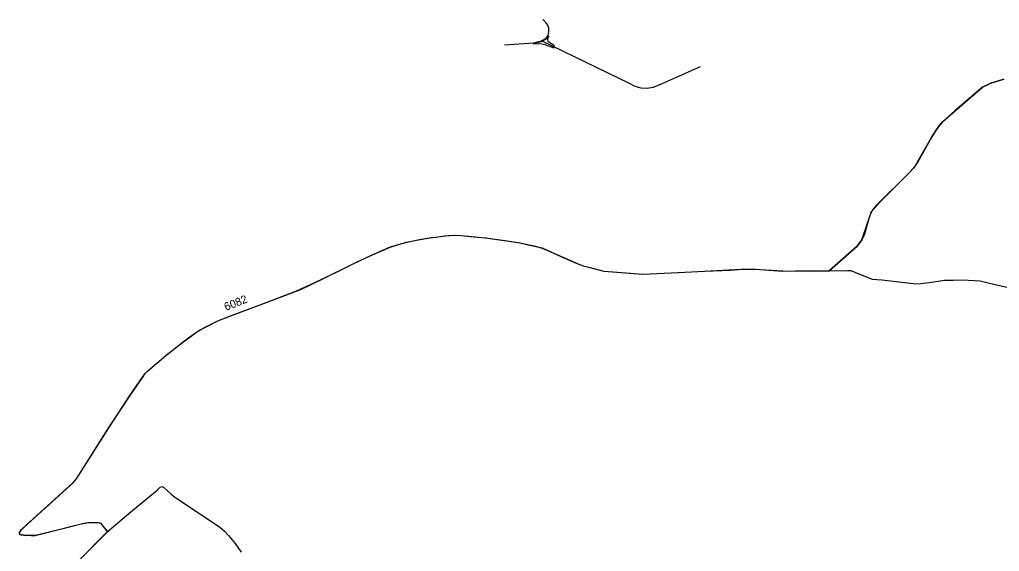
# Model space of a CAD drawing. Extents: x -444937 to -440733, y -1145714 to -1129798.
# Drawn here: x -444396 to -443173, y -1132712 to -1132048 of the extents above; entities that cross this region are included whole.
import ezdxf

# ---------------------------------------------------------------- set-up
doc = ezdxf.new("R2010")
doc.units = 0
doc.layers.add('Vrstva 12', color=7, linetype='Continuous')
doc.layers.add('Vrstva 75', color=7, linetype='Continuous')

msp = doc.modelspace()

# ---------------------------------------------------------------- linework, layer by layer
at = {"layer": 'Vrstva 12'}
for points in [[(-443790.5, -1132079.3), (-443754.5, -1132076.8), (-443744.6, -1132074.4), (-443738.7, -1132071), (-443736.3, -1132067.6), (-443735.4, -1132063.3), (-443735.4, -1132058.4), (-443736.6, -1132054.7), (-443739, -1132051.6), (-443742.8, -1132047.9)], [(-443546.4, -1132106.7), (-443594.8, -1132128.6), (-443605, -1132132.6), (-443612.4, -1132133.9), (-443620.1, -1132133.6), (-443627.5, -1132131.4), (-443635.5, -1132127.4), (-443744.6, -1132074.4)], [(-443167, -1132122.3), (-443176.2, -1132125.1), (-443183.1, -1132127.4), (-443193.7, -1132132.4), (-443228.1, -1132161.8), (-443243.2, -1132175.1), (-443248.2, -1132181.2), (-443252.1, -1132186.4), (-443257.1, -1132194.3), (-443275, -1132226.5), (-443280.2, -1132233.8), (-443285.8, -1132239.7), (-443325.5, -1132279.4), (-443330.7, -1132285.2), (-443333.2, -1132289.9), (-443335, -1132295.1), (-443341, -1132316.1), (-443344.2, -1132323), (-443350.1, -1132331.2), (-443385.1, -1132361.7)], [(-444286.4, -1132687.8), (-444291.4, -1132681.3), (-444294.5, -1132677.6), (-444297.8, -1132676.9), (-444301.8, -1132676.7), (-444311, -1132676.8), (-444317.7, -1132678.2), (-444337.3, -1132683), (-444376.8, -1132692.9), (-444381.9, -1132692.9), (-444386.3, -1132692.8), (-444390.1, -1132692.6), (-444391.2, -1132692.5), (-444394, -1132692.2), (-444394.6, -1132692.1), (-444395.8, -1132691.5), (-444396.3, -1132690.2), (-444396.3, -1132689.1), (-444395.6, -1132687.4), (-444390.6, -1132682), (-444328.9, -1132626.3), (-444325.6, -1132622.4), (-444322.2, -1132617.1), (-444284, -1132556.4), (-444258.4, -1132517.7), (-444241.6, -1132493.3), (-444239.4, -1132490.2), (-444236.1, -1132487), (-444213.9, -1132467.8), (-444192.2, -1132450.5), (-444183.6, -1132444.3), (-444175.6, -1132438.3), (-444169.9, -1132435.3), (-444163, -1132431.6), (-444149.6, -1132424.7), (-444139, -1132420.5), (-444097.1, -1132404.7), (-444046.4, -1132385.5), (-444034.5, -1132380.2), (-443993, -1132359.6), (-443976.4, -1132351.6), (-443958.6, -1132343.2), (-443943.2, -1132336.5), (-443933.5, -1132332.2), (-443923.2, -1132329), (-443913, -1132326.1), (-443900.5, -1132323.4), (-443884.1, -1132320.4), (-443873.9, -1132319.3)], [(-443873.9, -1132319.3), (-443860.9, -1132317.8), (-443853.7, -1132317.1), (-443845.1, -1132317.7), (-443829, -1132319.2), (-443813.9, -1132320.8), (-443787.5, -1132324.4), (-443774.1, -1132326.5), (-443765.9, -1132328.1), (-443753.7, -1132330.8), (-443743.6, -1132333.5), (-443718.8, -1132344.5), (-443697.9, -1132353.5), (-443692.3, -1132355.7), (-443687.3, -1132357), (-443666.5, -1132362.3), (-443654.9, -1132363.1), (-443618.1, -1132366.1), (-443573.6, -1132363.9), (-443540.7, -1132362.4), (-443508.2, -1132360.9), (-443493.5, -1132359.8), (-443478.8, -1132359.8), (-443442.9, -1132361.9), (-443404.8, -1132362.1), (-443385.1, -1132361.7), (-443362.3, -1132361.3), (-443358.1, -1132361.5), (-443353, -1132363.4), (-443331.5, -1132372.4), (-443319.2, -1132373.3), (-443276.5, -1132378.3), (-443271, -1132377.6), (-443259.7, -1132376.4), (-443241.2, -1132373.6), (-443230.1, -1132373.6), (-443218.9, -1132373.2), (-443203.8, -1132374.1), (-443196.6, -1132374.4), (-443184.8, -1132377.4), (-443145.3, -1132386.4)], [(-444323.9, -1132725.4), (-444287.2, -1132688.4), (-444257.5, -1132663.2), (-444224.7, -1132635.8), (-444220.9, -1132632.4), (-444218.5, -1132631.4), (-444216.2, -1132632.7), (-444211.7, -1132636.8), (-444207.2, -1132640.8), (-444202.9, -1132644.4), (-444146.1, -1132682.4), (-444140.4, -1132687.3), (-444135.5, -1132692.5), (-444127.1, -1132702.6), (-444119.5, -1132713.5)]]:
    msp.add_lwpolyline(points, dxfattribs=at)
msp.add_lwpolyline([(-443755, -1132078.3), (-443748.3, -1132077.9), (-443744.2, -1132078), (-443740.1, -1132078.9), (-443729, -1132083.2), (-443728.4, -1132080.7), (-443733.4, -1132077.4), (-443735.6, -1132075.6), (-443736.5, -1132074.1), (-443736.6, -1132072), (-443735.4, -1132068), (-443738.3, -1132072), (-443744.7, -1132075.7)], close=True, dxfattribs=at)
at = {"layer": 'Vrstva 75'}
for points in [[(-443385.1, -1132361.7), (-443350.1, -1132331.2), (-443344.2, -1132323), (-443337.2, -1132302.1), (-443332.4, -1132287.6), (-443320.7, -1132274.8), (-443285.8, -1132239.7), (-443278.5, -1132232.3), (-443257.1, -1132194.3), (-443248.2, -1132181.2), (-443243.2, -1132175.1), (-443193.7, -1132132.4), (-443183.1, -1132127.4), (-443167, -1132122.3)], [(-444286.2, -1132687.7), (-444291.4, -1132681.5), (-444294.5, -1132677.6), (-444297.1, -1132677), (-444301.1, -1132676.7), (-444310.3, -1132676.7), (-444314.3, -1132677.5), (-444319.4, -1132678.6), (-444334.8, -1132682.3), (-444342.5, -1132684.2), (-444376.4, -1132692.8), (-444385.1, -1132692.8), (-444390.9, -1132692.3), (-444394, -1132692.2), (-444395.5, -1132691.9), (-444396.4, -1132690.7), (-444396.3, -1132689.1), (-444393.8, -1132685.1), (-444388.2, -1132679.8), (-444330.1, -1132627.3), (-444325.6, -1132622.4), (-444322.2, -1132617.1), (-444284.1, -1132556.6), (-444258.5, -1132517.6), (-444241.9, -1132493.5), (-444239.4, -1132490.2), (-444237, -1132487.6), (-444213.5, -1132467.4), (-444191.4, -1132450), (-444183.9, -1132444.6), (-444175.6, -1132438.3), (-444170.8, -1132435.6), (-444162.5, -1132431.3), (-444149.6, -1132424.7), (-444136.2, -1132419.5), (-444097.1, -1132404.6), (-444051.4, -1132387.3), (-444028.3, -1132376.9), (-443993, -1132359.6), (-443978.7, -1132352.6), (-443957, -1132342.4), (-443938.2, -1132334.1), (-443933, -1132331.8), (-443921.8, -1132328.6), (-443910.6, -1132325.4), (-443897, -1132322.7), (-443882.1, -1132320.2), (-443876.5, -1132319.6)], [(-443876.5, -1132319.6), (-443865.6, -1132318.2), (-443853, -1132317.1), (-443845.1, -1132317.6), (-443826.9, -1132319.4), (-443811.3, -1132321.1), (-443785.2, -1132324.8), (-443771.1, -1132327), (-443762.6, -1132328.8), (-443749.6, -1132331.7), (-443743.6, -1132333.3), (-443721.3, -1132343.4), (-443714.3, -1132346.4), (-443701.3, -1132352.1), (-443692.3, -1132355.7), (-443680.6, -1132358.6), (-443666.5, -1132362.3), (-443618.4, -1132366.1), (-443573.2, -1132363.9), (-443540.7, -1132362.4), (-443495.2, -1132359.9), (-443487.2, -1132359.7), (-443477.2, -1132359.8), (-443443.5, -1132362.1), (-443427.3, -1132361.9), (-443399.8, -1132361.8), (-443365, -1132361.5)], [(-444323.9, -1132725.4), (-444286.2, -1132687.7)]]:
    msp.add_lwpolyline(points, dxfattribs=at)

# ---------------------------------------------------------------- texts
msp.add_text('6082', height=10, rotation=21.5484, dxfattribs=at).set_placement((-444138.5, -1132411.9))

doc.saveas('drawing.dxf')
